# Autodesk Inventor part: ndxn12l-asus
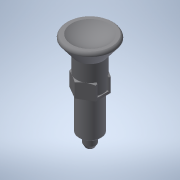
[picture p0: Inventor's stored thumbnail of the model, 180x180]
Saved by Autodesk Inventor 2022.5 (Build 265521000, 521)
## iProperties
Created: 2016-12
Part Number: ndxn12l-asus
Material: 一般
Document SubType Name: Modeling
Designer: imaocorp
Density: 1 g/cm^3
Appearance: 既定
Author: imaocorp
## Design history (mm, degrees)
node "ndxn12l-asus.x_t1"
node "ndxn12l-asus"
node "Base1"
